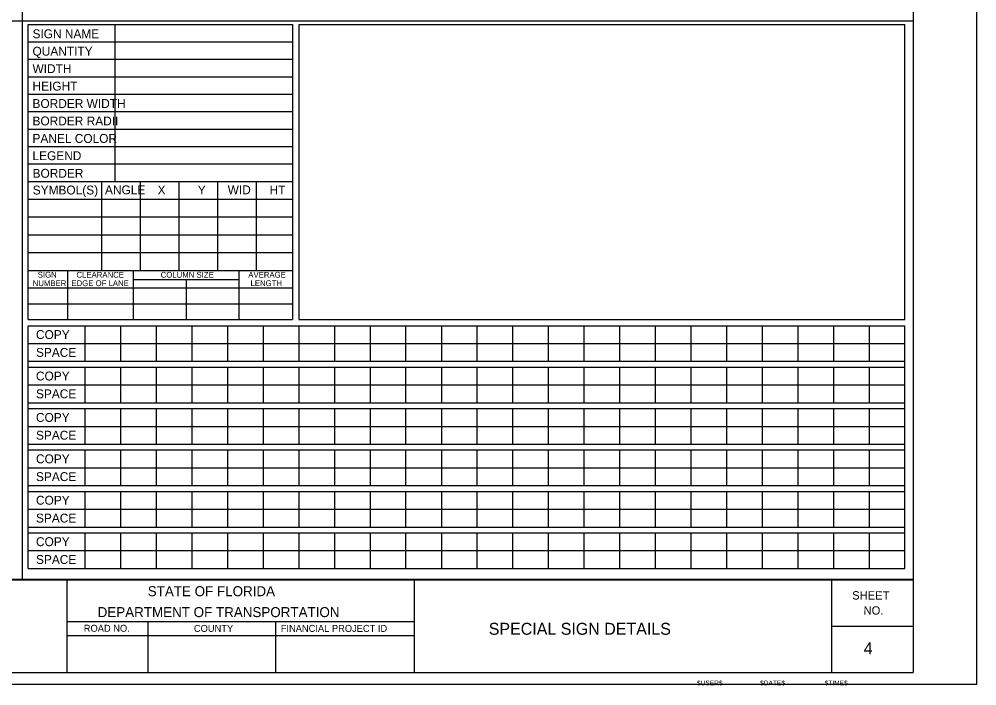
# Model space of a CAD drawing. Extents: x 17890628 to 17890844, y 17897693 to 17898031.
# Drawn here: x 17890772.1 to 17890844, y 17897907.5 to 17897957.5 of the extents above; entities that cross this region are included whole.
import ezdxf

# ---------------------------------------------------------------- set-up
doc = ezdxf.new("R2010")
doc.units = 0
for name, color, linetype in [('PlotBorder_dp', 7, 'Continuous'), ('SheetBorder_dp', 7, 'Continuous'), ('SheetLines_dp', 7, 'Continuous'), ('SheetLinesMisc2_dp', 7, 'Continuous'), ('TextMinor', 7, 'Continuous'), ('TextMisc', 7, 'Continuous')]:
    doc.layers.add(name, color=color, linetype=linetype)

msp = doc.modelspace()

# ---------------------------------------------------------------- linework, layer by layer
at = {"layer": 'PlotBorder_dp'}
msp.add_lwpolyline([(17890700.471, 17897907.61), (17890843.989, 17897907.61), (17890843.989, 17897999.809), (17890700.471, 17897999.809)], close=True, dxfattribs=at)
at = {"layer": 'SheetBorder_dp'}
for p, q in [((17890839.205, 17897998.94), (17890839.205, 17897908.479)), ((17890705.254, 17897915.438), (17890839.205, 17897915.438)), ((17890705.254, 17897908.479), (17890839.205, 17897908.479))]:
    msp.add_line(p, q, dxfattribs=at)
at = {"layer": 'SheetLines_dp'}
for p, q in [((17890775.709, 17897915.438), (17890775.709, 17897908.479)), ((17890801.803, 17897908.479), (17890801.803, 17897915.438)), ((17890833.116, 17897908.479), (17890833.116, 17897915.438)), ((17890775.709, 17897912.307), (17890801.803, 17897912.307)), ((17890781.798, 17897912.307), (17890781.798, 17897908.479)), ((17890791.366, 17897912.307), (17890791.366, 17897908.479)), ((17890833.116, 17897911.959), (17890839.205, 17897911.959)), ((17890775.709, 17897911.263), (17890801.803, 17897911.263))]:
    msp.add_line(p, q, dxfattribs=at)
at = {"layer": 'SheetLinesMisc2_dp'}
for p, q in [((17890772.367, 17897998.732), (17890772.367, 17897915.484)), ((17890839.233, 17897915.484), (17890839.233, 17897998.731)), ((17890705.5, 17897957.37), (17890839.233, 17897957.37)), ((17890772.823, 17897934.954), (17890772.823, 17897957.109)), ((17890772.823, 17897957.109), (17890792.654, 17897957.109)), ((17890779.324, 17897957.109), (17890779.324, 17897945.329)), ((17890792.654, 17897957.109), (17890792.654, 17897934.954)), ((17890793.11, 17897957.109), (17890793.11, 17897934.985)), ((17890793.11, 17897957.108), (17890838.594, 17897957.108)), ((17890838.594, 17897934.985), (17890838.594, 17897957.109)), ((17890772.823, 17897955.801), (17890792.654, 17897955.801)), ((17890772.823, 17897954.492), (17890792.654, 17897954.492)), ((17890772.823, 17897953.183), (17890792.654, 17897953.183)), ((17890772.823, 17897951.875), (17890792.654, 17897951.875)), ((17890772.823, 17897950.566), (17890792.654, 17897950.566)), ((17890772.823, 17897949.257), (17890792.654, 17897949.257)), ((17890772.823, 17897947.949), (17890782.738, 17897947.949)), ((17890782.738, 17897947.949), (17890792.654, 17897947.949)), ((17890772.823, 17897946.64), (17890782.738, 17897946.64)), ((17890782.738, 17897946.64), (17890792.654, 17897946.64)), ((17890772.823, 17897945.329), (17890792.654, 17897945.329)), ((17890778.326, 17897945.329), (17890778.326, 17897938.647)), ((17890781.223, 17897945.329), (17890781.223, 17897938.647)), ((17890784.121, 17897945.329), (17890784.121, 17897938.647)), ((17890787.018, 17897945.329), (17890787.018, 17897938.647)), ((17890789.916, 17897945.329), (17890789.916, 17897938.647)), ((17890772.823, 17897943.992), (17890792.654, 17897943.992)), ((17890772.823, 17897942.656), (17890792.654, 17897942.656)), ((17890772.823, 17897941.32), (17890792.654, 17897941.32)), ((17890772.823, 17897939.984), (17890792.654, 17897939.984)), ((17890772.823, 17897938.647), (17890792.654, 17897938.647)), ((17890775.761, 17897938.647), (17890775.761, 17897934.955)), ((17890780.696, 17897938.647), (17890780.696, 17897934.955)), ((17890788.628, 17897938.647), (17890788.628, 17897934.955)), ((17890780.696, 17897937.967), (17890788.628, 17897937.967)), ((17890784.663, 17897937.967), (17890784.663, 17897934.955)), ((17890772.823, 17897937.328), (17890792.654, 17897937.328)), ((17890772.823, 17897936.141), (17890792.654, 17897936.141)), ((17890772.823, 17897934.954), (17890792.654, 17897934.954)), ((17890793.11, 17897934.953), (17890838.594, 17897934.953)), ((17890838.594, 17897934.955), (17890838.594, 17897934.985)), ((17890772.824, 17897934.497), (17890838.594, 17897934.497)), ((17890772.824, 17897916.286), (17890772.824, 17897934.497)), ((17890777.058, 17897934.497), (17890777.058, 17897931.825)), ((17890779.733, 17897934.497), (17890779.733, 17897931.825)), ((17890782.408, 17897934.497), (17890782.408, 17897931.825)), ((17890785.084, 17897934.497), (17890785.084, 17897931.825)), ((17890787.76, 17897934.497), (17890787.76, 17897931.825)), ((17890790.435, 17897934.497), (17890790.435, 17897931.825)), ((17890793.11, 17897934.497), (17890793.11, 17897931.825)), ((17890795.786, 17897934.497), (17890795.786, 17897931.825)), ((17890798.462, 17897934.497), (17890798.462, 17897931.825)), ((17890801.137, 17897934.497), (17890801.137, 17897931.825)), ((17890803.813, 17897934.497), (17890803.813, 17897931.825)), ((17890806.488, 17897934.497), (17890806.488, 17897931.825)), ((17890809.164, 17897934.497), (17890809.164, 17897931.825)), ((17890811.839, 17897934.497), (17890811.839, 17897931.825)), ((17890814.514, 17897934.497), (17890814.514, 17897931.825)), ((17890817.19, 17897934.497), (17890817.19, 17897931.825)), ((17890819.866, 17897934.497), (17890819.866, 17897931.825)), ((17890822.541, 17897934.497), (17890822.541, 17897931.825)), ((17890825.216, 17897934.497), (17890825.216, 17897931.825)), ((17890827.892, 17897934.497), (17890827.892, 17897931.825)), ((17890830.568, 17897934.497), (17890830.568, 17897931.825)), ((17890833.243, 17897934.497), (17890833.243, 17897931.825)), ((17890835.919, 17897934.497), (17890835.919, 17897931.825)), ((17890838.594, 17897916.286), (17890838.594, 17897934.497)), ((17890772.824, 17897933.162), (17890838.594, 17897933.162)), ((17890772.824, 17897931.825), (17890838.594, 17897931.825)), ((17890772.824, 17897931.389), (17890838.594, 17897931.389)), ((17890777.058, 17897931.389), (17890777.058, 17897928.717)), ((17890779.733, 17897931.389), (17890779.733, 17897928.717)), ((17890782.408, 17897931.389), (17890782.408, 17897928.717)), ((17890785.084, 17897931.389), (17890785.084, 17897928.717)), ((17890787.76, 17897931.389), (17890787.76, 17897928.717)), ((17890790.435, 17897931.389), (17890790.435, 17897928.717)), ((17890793.11, 17897931.389), (17890793.11, 17897928.717)), ((17890795.786, 17897931.389), (17890795.786, 17897928.717)), ((17890798.462, 17897931.389), (17890798.462, 17897928.717)), ((17890801.137, 17897931.389), (17890801.137, 17897928.717)), ((17890803.813, 17897931.389), (17890803.813, 17897928.717)), ((17890806.488, 17897931.389), (17890806.488, 17897928.717)), ((17890809.164, 17897931.389), (17890809.164, 17897928.717)), ((17890811.839, 17897931.389), (17890811.839, 17897928.717)), ((17890814.514, 17897931.389), (17890814.514, 17897928.717)), ((17890817.19, 17897931.389), (17890817.19, 17897928.717)), ((17890819.866, 17897931.389), (17890819.866, 17897928.717)), ((17890822.541, 17897931.389), (17890822.541, 17897928.717)), ((17890825.216, 17897931.389), (17890825.216, 17897928.717)), ((17890827.892, 17897931.389), (17890827.892, 17897928.717)), ((17890830.568, 17897931.389), (17890830.568, 17897928.717)), ((17890833.243, 17897931.389), (17890833.243, 17897928.717)), ((17890835.919, 17897931.389), (17890835.919, 17897928.717)), ((17890772.824, 17897930.053), (17890838.594, 17897930.053)), ((17890772.824, 17897928.717), (17890838.594, 17897928.717)), ((17890772.824, 17897928.281), (17890838.594, 17897928.281)), ((17890777.058, 17897928.281), (17890777.058, 17897925.609)), ((17890779.733, 17897928.281), (17890779.733, 17897925.609)), ((17890782.408, 17897928.281), (17890782.408, 17897925.609)), ((17890785.084, 17897928.281), (17890785.084, 17897925.609)), ((17890787.76, 17897928.281), (17890787.76, 17897925.609)), ((17890790.435, 17897928.281), (17890790.435, 17897925.609)), ((17890793.11, 17897928.281), (17890793.11, 17897925.609)), ((17890795.786, 17897928.281), (17890795.786, 17897925.609)), ((17890798.462, 17897928.281), (17890798.462, 17897925.609)), ((17890801.137, 17897928.281), (17890801.137, 17897925.609)), ((17890803.813, 17897928.281), (17890803.813, 17897925.609)), ((17890806.488, 17897928.281), (17890806.488, 17897925.609)), ((17890809.164, 17897928.281), (17890809.164, 17897925.609)), ((17890811.839, 17897928.281), (17890811.839, 17897925.609)), ((17890814.514, 17897928.281), (17890814.514, 17897925.609)), ((17890817.19, 17897928.281), (17890817.19, 17897925.609)), ((17890819.866, 17897928.281), (17890819.866, 17897925.609)), ((17890822.541, 17897928.281), (17890822.541, 17897925.609)), ((17890825.216, 17897928.281), (17890825.216, 17897925.609)), ((17890827.892, 17897928.281), (17890827.892, 17897925.609)), ((17890830.568, 17897928.281), (17890830.568, 17897925.609)), ((17890833.243, 17897928.281), (17890833.243, 17897925.609)), ((17890835.919, 17897928.281), (17890835.919, 17897925.609)), ((17890772.824, 17897926.945), (17890838.594, 17897926.945)), ((17890772.824, 17897925.609), (17890838.594, 17897925.609)), ((17890772.824, 17897925.173), (17890838.594, 17897925.173)), ((17890777.058, 17897925.173), (17890777.058, 17897922.501)), ((17890779.733, 17897925.173), (17890779.733, 17897922.501)), ((17890782.408, 17897925.173), (17890782.408, 17897922.501)), ((17890785.084, 17897925.173), (17890785.084, 17897922.501)), ((17890787.76, 17897925.173), (17890787.76, 17897922.501)), ((17890790.435, 17897925.173), (17890790.435, 17897922.501)), ((17890793.11, 17897925.173), (17890793.11, 17897922.501)), ((17890795.786, 17897925.173), (17890795.786, 17897922.501)), ((17890798.462, 17897925.173), (17890798.462, 17897922.501)), ((17890801.137, 17897925.173), (17890801.137, 17897922.501)), ((17890803.813, 17897925.173), (17890803.813, 17897922.501)), ((17890806.488, 17897925.173), (17890806.488, 17897922.501)), ((17890809.164, 17897925.173), (17890809.164, 17897922.501)), ((17890811.839, 17897925.173), (17890811.839, 17897922.501)), ((17890814.514, 17897925.173), (17890814.514, 17897922.501)), ((17890817.19, 17897925.173), (17890817.19, 17897922.501)), ((17890819.866, 17897925.173), (17890819.866, 17897922.501)), ((17890822.541, 17897925.173), (17890822.541, 17897922.501)), ((17890825.216, 17897925.173), (17890825.216, 17897922.501)), ((17890827.892, 17897925.173), (17890827.892, 17897922.501)), ((17890830.568, 17897925.173), (17890830.568, 17897922.501)), ((17890833.243, 17897925.173), (17890833.243, 17897922.501)), ((17890835.919, 17897925.173), (17890835.919, 17897922.501)), ((17890772.824, 17897923.838), (17890838.594, 17897923.838)), ((17890772.824, 17897922.501), (17890838.594, 17897922.501)), ((17890772.824, 17897922.065), (17890838.594, 17897922.065)), ((17890777.058, 17897922.065), (17890777.058, 17897919.393)), ((17890779.733, 17897922.065), (17890779.733, 17897919.393)), ((17890782.408, 17897922.065), (17890782.408, 17897919.393)), ((17890785.084, 17897922.065), (17890785.084, 17897919.393)), ((17890787.76, 17897922.065), (17890787.76, 17897919.393)), ((17890790.435, 17897922.065), (17890790.435, 17897919.393)), ((17890793.11, 17897922.065), (17890793.11, 17897919.393)), ((17890795.786, 17897922.065), (17890795.786, 17897919.393)), ((17890798.462, 17897922.065), (17890798.462, 17897919.393)), ((17890801.137, 17897922.065), (17890801.137, 17897919.393)), ((17890803.813, 17897922.065), (17890803.813, 17897919.393)), ((17890806.488, 17897922.065), (17890806.488, 17897919.393)), ((17890809.164, 17897922.065), (17890809.164, 17897919.393)), ((17890811.839, 17897922.065), (17890811.839, 17897919.393)), ((17890814.514, 17897922.065), (17890814.514, 17897919.393)), ((17890817.19, 17897922.065), (17890817.19, 17897919.393)), ((17890819.866, 17897922.065), (17890819.866, 17897919.393)), ((17890822.541, 17897922.065), (17890822.541, 17897919.393)), ((17890825.216, 17897922.065), (17890825.216, 17897919.393)), ((17890827.892, 17897922.065), (17890827.892, 17897919.393)), ((17890830.568, 17897922.065), (17890830.568, 17897919.393)), ((17890833.243, 17897922.065), (17890833.243, 17897919.393)), ((17890835.919, 17897922.065), (17890835.919, 17897919.393)), ((17890772.824, 17897920.729), (17890838.594, 17897920.729)), ((17890772.824, 17897919.393), (17890838.594, 17897919.393)), ((17890772.824, 17897918.958), (17890838.594, 17897918.958)), ((17890777.058, 17897918.958), (17890777.058, 17897916.286)), ((17890779.733, 17897918.958), (17890779.733, 17897916.286)), ((17890782.408, 17897918.958), (17890782.408, 17897916.286)), ((17890785.084, 17897918.958), (17890785.084, 17897916.286)), ((17890787.76, 17897918.958), (17890787.76, 17897916.286)), ((17890790.435, 17897918.958), (17890790.435, 17897916.286)), ((17890793.11, 17897918.958), (17890793.11, 17897916.286)), ((17890795.786, 17897918.958), (17890795.786, 17897916.286)), ((17890798.462, 17897918.958), (17890798.462, 17897916.286)), ((17890801.137, 17897918.958), (17890801.137, 17897916.286)), ((17890803.813, 17897918.958), (17890803.813, 17897916.286)), ((17890806.488, 17897918.958), (17890806.488, 17897916.286)), ((17890809.164, 17897918.958), (17890809.164, 17897916.286)), ((17890811.839, 17897918.958), (17890811.839, 17897916.286)), ((17890814.514, 17897918.958), (17890814.514, 17897916.286)), ((17890817.19, 17897918.958), (17890817.19, 17897916.286)), ((17890819.866, 17897918.958), (17890819.866, 17897916.286)), ((17890822.541, 17897918.958), (17890822.541, 17897916.286)), ((17890825.216, 17897918.958), (17890825.216, 17897916.286)), ((17890827.892, 17897918.958), (17890827.892, 17897916.286)), ((17890830.568, 17897918.958), (17890830.568, 17897916.286)), ((17890833.243, 17897918.958), (17890833.243, 17897916.286)), ((17890835.919, 17897918.958), (17890835.919, 17897916.286)), ((17890772.824, 17897917.622), (17890838.594, 17897917.622)), ((17890772.824, 17897916.286), (17890838.594, 17897916.286)), ((17890705.5, 17897915.484), (17890839.233, 17897915.484))]:
    msp.add_line(p, q, dxfattribs=at)

# ---------------------------------------------------------------- texts
at = {"layer": 'TextMinor'}
for s, height, p in [('SIGN NAME', 0.6667, (17890773.142, 17897956.069)), ('QUANTITY', 0.6667, (17890773.142, 17897954.761)), ('WIDTH', 0.6667, (17890773.142, 17897953.452)), ('HEIGHT', 0.6667, (17890773.142, 17897952.144)), ('BORDER WIDTH', 0.66667, (17890773.142, 17897950.835)), ('BORDER RADII', 0.66667, (17890773.142, 17897949.526)), ('PANEL COLOR', 0.66667, (17890773.142, 17897948.218)), ('LEGEND', 0.6667, (17890773.142, 17897946.921)), ('BORDER', 0.6667, (17890773.148, 17897945.6)), ('SYMBOL(S)', 0.6667, (17890773.16, 17897944.346)), ('ANGLE', 0.6667, (17890778.58, 17897944.36)), ('X', 0.667, (17890782.527, 17897944.346)), ('Y', 0.667, (17890785.54, 17897944.346)), ('WID', 0.6667, (17890787.784, 17897944.36)), ('HT', 0.6667, (17890790.925, 17897944.348)), ('SIGN', 0.4357, (17890773.533, 17897938.103)), ('CLEARANCE', 0.4357, (17890776.44, 17897938.101)), ('COLUMN SIZE', 0.43573, (17890782.758, 17897938.101)), ('AVERAGE', 0.4357, (17890789.329, 17897938.101)), ('NUMBER', 0.4357, (17890773.154, 17897937.469)), ('EDGE OF LANE', 0.43573, (17890776.061, 17897937.469)), ('LENGTH', 0.4357, (17890789.498, 17897937.469)), ('COPY', 0.6667, (17890773.402, 17897933.498)), ('SPACE', 0.6667, (17890773.402, 17897932.162)), ('COPY', 0.6667, (17890773.402, 17897930.389)), ('SPACE', 0.6667, (17890773.402, 17897929.053)), ('COPY', 0.6667, (17890773.402, 17897927.282)), ('SPACE', 0.6667, (17890773.402, 17897925.946)), ('COPY', 0.6667, (17890773.402, 17897924.173)), ('SPACE', 0.6667, (17890773.402, 17897922.838)), ('COPY', 0.6667, (17890773.402, 17897921.065)), ('SPACE', 0.6667, (17890773.402, 17897919.729)), ('COPY', 0.6667, (17890773.402, 17897917.958)), ('SPACE', 0.6667, (17890773.402, 17897916.622))]:
    msp.add_text(s, height=height, dxfattribs=at).set_placement(p)
at = {"layer": 'TextMisc'}
for s, height, p in [('STATE OF FLORIDA', 0.75151, (17890781.788, 17897914.2)), ('DEPARTMENT OF TRANSPORTATION', 0.75151, (17890778.029, 17897912.63)), ('ROAD NO.', 0.5219, (17890776.988, 17897911.533)), ('COUNTY', 0.5219, (17890785.251, 17897911.524)), ('FINANCIAL PROJECT ID', 0.52189, (17890791.765, 17897911.524)), ('SPECIAL SIGN DETAILS', 0.89699, (17890807.369, 17897911.305)), ('4', 0.897, (17890835.5, 17897909.843)), ('$USER$', 0.3588, (17890822.99, 17897907.509)), ('$DATE$', 0.3588, (17890827.724, 17897907.509)), ('$TIME$', 0.3588, (17890832.57, 17897907.509))]:
    msp.add_text(s, height=height, dxfattribs=at).set_placement(p)
for s, p in [('SHEET', (17890834.639, 17897913.951)), ('NO.', (17890835.491, 17897912.82))]:
    msp.add_text(s, height=0.6263, rotation=359.86066, dxfattribs=at).set_placement(p)

doc.saveas('drawing.dxf')
